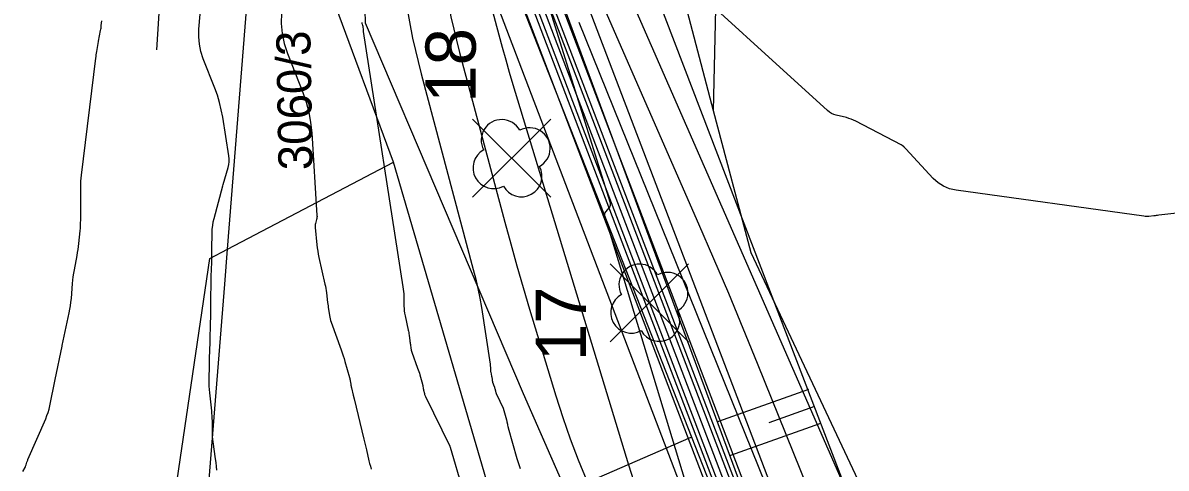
# Model space of a CAD drawing. Extents: x -534410 to -534262, y -1190162 to -1189584.
# Drawn here: x -534375.72 to -534347.25, y -1189924.89 to -1189913.8 of the extents above; entities that cross this region are included whole.
import ezdxf

# ---------------------------------------------------------------- set-up
doc = ezdxf.new("R2010")
doc.units = 0
for name, color, linetype in [('30', 7, 'Continuous'), ('31', 7, 'Continuous'), ('_linie', 7, 'Continuous'), ('_N_osa', 7, 'Continuous'), ('_N_tenká', 7, 'Continuous'), ('_N_tenká_velmi', 7, 'Continuous'), ('_přístup', 7, 'Continuous'), ('_tenka', 7, 'Continuous'), ('_velmi_tenka', 7, 'Continuous'), ('Default', 7, 'Continuous'), ('Hranice parcel', 7, 'Continuous'), ('Parcelní čísla', 7, 'Continuous')]:
    doc.layers.add(name, color=color, linetype=linetype)

msp = doc.modelspace()

# ---------------------------------------------------------------- linework, layer by layer
at = {"layer": '30'}
for points in [[(-534366.318, -1189889.293), (-534365.402, -1189910.932), (-534365.338, -1189911.844), (-534365.225, -1189912.749), (-534365.062, -1189913.646), (-534364.85, -1189914.535), (-534363.721, -1189918.76), (-534363.573, -1189919.304), (-534363.42, -1189919.847), (-534363.263, -1189920.389), (-534363.101, -1189920.929), (-534362.446, -1189923.087), (-534362.275, -1189923.625), (-534362.09, -1189924.157), (-534361.891, -1189924.684), (-534361.678, -1189925.205), (-534360.07, -1189929.007)], [(-534370.89, -1189924.938), (-534370.899, -1189924.845), (-534370.909, -1189924.752), (-534370.922, -1189924.659), (-534370.983, -1189924.231), (-534370.991, -1189924.167), (-534370.997, -1189924.103), (-534371, -1189924.038), (-534371.001, -1189923.974), (-534371.001, -1189923.715), (-534371.002, -1189923.651), (-534371.005, -1189923.586), (-534371.01, -1189923.522), (-534371.016, -1189923.458), (-534371.066, -1189923.011), (-534371.074, -1189922.928), (-534371.079, -1189922.844), (-534371.081, -1189922.761), (-534371.081, -1189922.677), (-534371.075, -1189922.334), (-534371.074, -1189922.254), (-534371.072, -1189922.174), (-534371.07, -1189922.094), (-534371.067, -1189922.015), (-534371.056, -1189921.696), (-534371.054, -1189921.616), (-534371.052, -1189921.536), (-534371.05, -1189921.457), (-534371.048, -1189921.377), (-534371.042, -1189921.018), (-534371.041, -1189920.931), (-534371.04, -1189920.844), (-534371.038, -1189920.758), (-534371.037, -1189920.671), (-534371.032, -1189920.271), (-534371.031, -1189920.201), (-534371.029, -1189920.131), (-534371.028, -1189920.061), (-534371.026, -1189919.992), (-534371.018, -1189919.713), (-534371.017, -1189919.643), (-534371.015, -1189919.573), (-534371.014, -1189919.503), (-534371.013, -1189919.434), (-534371.007, -1189919.027), (-534371.003, -1189918.936), (-534370.993, -1189918.846), (-534370.978, -1189918.757), (-534370.957, -1189918.669), (-534370.737, -1189917.857), (-534370.728, -1189917.826), (-534370.61, -1189917.403), (-534370.594, -1189917.331), (-534370.585, -1189917.259), (-534370.585, -1189917.186), (-534370.593, -1189917.113), (-534370.744, -1189916.148), (-534370.778, -1189915.964), (-534370.822, -1189915.783), (-534370.876, -1189915.604), (-534370.939, -1189915.428), (-534371.227, -1189914.698), (-534371.287, -1189914.516), (-534371.325, -1189914.332), (-534371.341, -1189914.144), (-534371.335, -1189913.953), (-534371.182, -1189912.181)], [(-534362.891, -1189912.541), (-534361.099, -1189918.283), (-534361.093, -1189918.315), (-534361.094, -1189918.345), (-534361.104, -1189918.373), (-534361.122, -1189918.401), (-534361.208, -1189918.506), (-534361.226, -1189918.533), (-534361.235, -1189918.562), (-534361.237, -1189918.592), (-534361.231, -1189918.624), (-534358.587, -1189927.327), (-534358.507, -1189927.579), (-534358.42, -1189927.829), (-534358.327, -1189928.076), (-534358.227, -1189928.32), (-534357.815, -1189929.294), (-534357.714, -1189929.539), (-534357.619, -1189929.785), (-534357.528, -1189930.033), (-534357.442, -1189930.283), (-534355.441, -1189936.3), (-534355.266, -1189936.801)], [(-534355.227, -1189925.422), (-534360.506, -1189913.368)], [(-534367.28, -1189913.791), (-534367.28, -1189913.8), (-534367.279, -1189913.81), (-534367.277, -1189913.82), (-534367.274, -1189913.829), (-534367.26, -1189913.867), (-534367.256, -1189913.876), (-534367.254, -1189913.886), (-534367.252, -1189913.895), (-534367.251, -1189913.905), (-534367.247, -1189913.961), (-534367.247, -1189913.974), (-534367.245, -1189913.986), (-534367.244, -1189913.999), (-534367.242, -1189914.012), (-534366.255, -1189920.37), (-534366.246, -1189920.429), (-534366.24, -1189920.49), (-534366.236, -1189920.55), (-534366.234, -1189920.61), (-534366.231, -1189920.853), (-534366.229, -1189920.913), (-534366.224, -1189920.973), (-534366.215, -1189921.033), (-534366.204, -1189921.092), (-534366.124, -1189921.45), (-534366.117, -1189921.481), (-534366.112, -1189921.512), (-534366.107, -1189921.544), (-534366.102, -1189921.575), (-534366.085, -1189921.715), (-534366.082, -1189921.739), (-534366.078, -1189921.763), (-534366.075, -1189921.787), (-534366.071, -1189921.81), (-534366.057, -1189921.906), (-534366.053, -1189921.929), (-534366.047, -1189921.953), (-534366.041, -1189921.976), (-534366.034, -1189921.998), (-534365.889, -1189922.401), (-534365.875, -1189922.443), (-534365.861, -1189922.485), (-534365.847, -1189922.527), (-534365.835, -1189922.569), (-534365.768, -1189922.8), (-534365.765, -1189922.812), (-534365.762, -1189922.824), (-534365.759, -1189922.836), (-534365.757, -1189922.849), (-534365.75, -1189922.898), (-534365.748, -1189922.91), (-534365.746, -1189922.922), (-534365.743, -1189922.935), (-534365.741, -1189922.947), (-534365.72, -1189923.034), (-534365.715, -1189923.052), (-534365.709, -1189923.07), (-534365.702, -1189923.088), (-534365.694, -1189923.105), (-534365.088, -1189924.346), (-534365.086, -1189924.351), (-534365.082, -1189924.367), (-534364.772, -1189925.413)], [(-534350.654, -1189940.266), (-534350.975, -1189939.571), (-534351.3, -1189938.876), (-534354.616, -1189931.824), (-534354.78, -1189931.466), (-534354.936, -1189931.106), (-534355.086, -1189930.743), (-534355.228, -1189930.376), (-534355.784, -1189928.905), (-534355.924, -1189928.537), (-534356.066, -1189928.171), (-534356.21, -1189927.805), (-534356.356, -1189927.44), (-534361.865, -1189913.788)]]:
    msp.add_lwpolyline(points, dxfattribs=at)
at = {"layer": '31'}
for points in [[(-534346.245, -1189918.455), (-534347.437, -1189918.593), (-534347.468, -1189918.596), (-534347.498, -1189918.6), (-534347.529, -1189918.603), (-534347.56, -1189918.606), (-534347.682, -1189918.619), (-534347.712, -1189918.622), (-534347.743, -1189918.622), (-534347.774, -1189918.621), (-534347.804, -1189918.617), (-534352.484, -1189917.968), (-534352.646, -1189917.932), (-534352.794, -1189917.871), (-534352.929, -1189917.785), (-534353.051, -1189917.673), (-534353.733, -1189916.936), (-534353.748, -1189916.92), (-534353.772, -1189916.893), (-534353.777, -1189916.888), (-534353.782, -1189916.883), (-534353.787, -1189916.879), (-534353.793, -1189916.875), (-534353.823, -1189916.854), (-534353.83, -1189916.849), (-534353.837, -1189916.845), (-534353.844, -1189916.841), (-534353.852, -1189916.837), (-534354.975, -1189916.251), (-534355.033, -1189916.223), (-534355.093, -1189916.199), (-534355.153, -1189916.178), (-534355.215, -1189916.161), (-534355.466, -1189916.099), (-534355.527, -1189916.08), (-534355.584, -1189916.054), (-534355.637, -1189916.021), (-534355.687, -1189915.981), (-534359.811, -1189912.222)], [(-534364.201, -1189912.857), (-534363.869, -1189914.099), (-534363.784, -1189914.409), (-534363.697, -1189914.719), (-534363.608, -1189915.027), (-534363.516, -1189915.335), (-534360.637, -1189924.81), (-534360.449, -1189925.402), (-534360.245, -1189925.989), (-534360.026, -1189926.57), (-534359.791, -1189927.145), (-534359.16, -1189928.636)], [(-534366.182, -1189913.277), (-534366.018, -1189914.179), (-534365.805, -1189915.073), (-534364.503, -1189919.944), (-534364.443, -1189920.179), (-534364.39, -1189920.415), (-534364.343, -1189920.653), (-534364.303, -1189920.892), (-534364.085, -1189922.297), (-534364.082, -1189922.314), (-534364.081, -1189922.33), (-534364.08, -1189922.347), (-534364.079, -1189922.364), (-534364.078, -1189922.43), (-534364.078, -1189922.447), (-534364.076, -1189922.464), (-534364.074, -1189922.48), (-534364.071, -1189922.496), (-534364.049, -1189922.595), (-534364.047, -1189922.604), (-534364.045, -1189922.612), (-534364.044, -1189922.621), (-534364.043, -1189922.629), (-534364.037, -1189922.674), (-534364.034, -1189922.694), (-534364.03, -1189922.72), (-534364.029, -1189922.727), (-534364.028, -1189922.733), (-534364.026, -1189922.74), (-534364.024, -1189922.746), (-534363.984, -1189922.857), (-534363.98, -1189922.868), (-534363.976, -1189922.88), (-534363.972, -1189922.891), (-534363.969, -1189922.903), (-534363.951, -1189922.967), (-534363.949, -1189922.973), (-534363.948, -1189922.98), (-534363.945, -1189922.997), (-534363.943, -1189923.007), (-534363.937, -1189923.031), (-534363.936, -1189923.036), (-534363.934, -1189923.041), (-534363.932, -1189923.046), (-534363.93, -1189923.051), (-534363.763, -1189923.392), (-534363.762, -1189923.398), (-534363.676, -1189923.686), (-534363.673, -1189923.698), (-534363.67, -1189923.709), (-534363.668, -1189923.72), (-534363.665, -1189923.732), (-534363.653, -1189923.793), (-534363.649, -1189923.818), (-534363.643, -1189923.851), (-534363.641, -1189923.86), (-534363.639, -1189923.868), (-534363.637, -1189923.876), (-534363.635, -1189923.885), (-534363.416, -1189924.645), (-534363.377, -1189924.774), (-534363.335, -1189924.901)], [(-534350.063, -1189940.058), (-534350.26, -1189939.632), (-534350.459, -1189939.207), (-534352.036, -1189935.853), (-534352.358, -1189935.15), (-534352.667, -1189934.44), (-534352.961, -1189933.725), (-534353.242, -1189933.004), (-534354.655, -1189929.263), (-534354.984, -1189928.399), (-534355.318, -1189927.536), (-534355.657, -1189926.676), (-534356, -1189925.818), (-534357.425, -1189922.287), (-534357.781, -1189921.414), (-534358.143, -1189920.544), (-534358.512, -1189919.677), (-534358.887, -1189918.812), (-534361.396, -1189913.081)], [(-534369.28, -1189913.554), (-534369.288, -1189913.812), (-534369.266, -1189914.066), (-534369.215, -1189914.315), (-534369.134, -1189914.56), (-534368.751, -1189915.532), (-534368.666, -1189915.778), (-534368.6, -1189916.027), (-534368.554, -1189916.281), (-534368.527, -1189916.54), (-534368.396, -1189918.597), (-534368.395, -1189918.623), (-534368.397, -1189918.648), (-534368.4, -1189918.673), (-534368.406, -1189918.697), (-534368.433, -1189918.795), (-534368.438, -1189918.82), (-534368.442, -1189918.845), (-534368.443, -1189918.87), (-534368.441, -1189918.895), (-534368.398, -1189919.324), (-534368.389, -1189919.404), (-534368.377, -1189919.483), (-534368.364, -1189919.562), (-534368.347, -1189919.64), (-534368.199, -1189920.306), (-534368.188, -1189920.359), (-534368.178, -1189920.413), (-534368.169, -1189920.466), (-534368.162, -1189920.52), (-534368.132, -1189920.762), (-534368.126, -1189920.803), (-534368.121, -1189920.844), (-534368.115, -1189920.886), (-534368.109, -1189920.927), (-534368.084, -1189921.091), (-534368.077, -1189921.131), (-534368.067, -1189921.172), (-534368.056, -1189921.212), (-534368.043, -1189921.251), (-534367.795, -1189921.945), (-534367.769, -1189922.017), (-534367.745, -1189922.089), (-534367.722, -1189922.162), (-534367.701, -1189922.235), (-534367.585, -1189922.633), (-534367.579, -1189922.654), (-534367.575, -1189922.675), (-534367.57, -1189922.696), (-534367.567, -1189922.717), (-534367.555, -1189922.802), (-534367.551, -1189922.823), (-534367.547, -1189922.844), (-534367.543, -1189922.865), (-534367.538, -1189922.886), (-534367.495, -1189923.069), (-534367.472, -1189923.165), (-534367.232, -1189924.165), (-534367.167, -1189924.437), (-534367.102, -1189924.709), (-534367.085, -1189924.776), (-534367.067, -1189924.844), (-534367.049, -1189924.911)], [(-534375.719, -1189924.973), (-534375.665, -1189924.876), (-534375.657, -1189924.86), (-534375.65, -1189924.844), (-534375.643, -1189924.827), (-534375.638, -1189924.81), (-534375.617, -1189924.742), (-534375.612, -1189924.725), (-534375.606, -1189924.709), (-534375.599, -1189924.692), (-534375.593, -1189924.676), (-534375.15, -1189923.659), (-534375.119, -1189923.581), (-534375.091, -1189923.502), (-534375.068, -1189923.422), (-534375.049, -1189923.34), (-534374.913, -1189922.679), (-534374.741, -1189921.848), (-534374.739, -1189921.839), (-534374.565, -1189921.022), (-534374.548, -1189920.933), (-534374.533, -1189920.844), (-534374.521, -1189920.754), (-534374.512, -1189920.663), (-534374.482, -1189920.292), (-534374.473, -1189920.206), (-534374.463, -1189920.121), (-534374.45, -1189920.036), (-534374.436, -1189919.951), (-534374.368, -1189919.59), (-534374.355, -1189919.516), (-534374.344, -1189919.442), (-534374.334, -1189919.367), (-534374.326, -1189919.293), (-534374.294, -1189918.978), (-534374.288, -1189918.911), (-534374.284, -1189918.844), (-534374.281, -1189918.777), (-534374.28, -1189918.711), (-534374.279, -1189918.443), (-534374.279, -1189918.376), (-534374.279, -1189918.309), (-534374.279, -1189918.242), (-534374.279, -1189918.175), (-534374.279, -1189917.881), (-534374.278, -1189917.81), (-534374.275, -1189917.739), (-534374.269, -1189917.668), (-534374.261, -1189917.597), (-534373.902, -1189914.678), (-534373.896, -1189914.637), (-534373.891, -1189914.595), (-534373.885, -1189914.553), (-534373.878, -1189914.512), (-534373.84, -1189914.263), (-534373.839, -1189914.259), (-534373.784, -1189913.987), (-534373.778, -1189913.958), (-534373.773, -1189913.928), (-534373.769, -1189913.898), (-534373.766, -1189913.868), (-534373.753, -1189913.749)]]:
    msp.add_lwpolyline(points, dxfattribs=at)
at = {"layer": '_linie'}
for points in [[(-534366.12, -1189620.81), (-534364.52, -1189627.2), (-534365.69, -1189653.8), (-534366.76, -1189684.81), (-534368.14, -1189748.73), (-534368.38, -1189779.14), (-534368.65, -1189820.64), (-534368.59, -1189847.58), (-534367.2, -1189913.8)], [(-534363.12, -1189621.02), (-534362.79, -1189621.58), (-534361.82, -1189627.79), (-534363.46, -1189653.55), (-534365.47, -1189684.77), (-534366.65, -1189748.83), (-534366.75, -1189779.47), (-534366.9, -1189820.47), (-534366.95, -1189846.72), (-534366.338, -1189888.804), (-534363.85, -1189911.95), (-534357.07, -1189929.19), (-534352.334, -1189940.856)], [(-534359.03, -1189621.26), (-534359.41, -1189621.83), (-534360.84, -1189627.76), (-534362.92, -1189653.56), (-534364.64, -1189685), (-534365.94, -1189748.9), (-534366.02, -1189779.52), (-534366.03, -1189820.5), (-534366.48, -1189846.73), (-534365.511, -1189888.873), (-534362.72, -1189912.12), (-534356.62, -1189928.64), (-534351.589, -1189940.594)], [(-534367.2, -1189913.8), (-534363.26, -1189923.03), (-534359.43, -1189931.78), (-534354.79, -1189941.72)]]:
    msp.add_lwpolyline(points, dxfattribs=at)
at = {"layer": '_N_osa'}
msp.add_lwpolyline([(-534351.95, -1189940.722), (-534356.845, -1189928.915), (-534363.285, -1189912.035), (-534365.925, -1189888.838), (-534366.715, -1189846.725), (-534366.465, -1189820.485), (-534366.385, -1189779.495), (-534366.295, -1189748.865), (-534365.055, -1189684.885), (-534363.19, -1189653.555), (-534361.333, -1189627.822)], dxfattribs=at)
at = {"layer": '_N_tenká'}
for points in [[(-534352.92, -1189941.124), (-534357.821, -1189929.303), (-534364.313, -1189912.285), (-534366.973, -1189888.908), (-534367.765, -1189846.73), (-534367.515, -1189820.479), (-534367.435, -1189779.492), (-534367.345, -1189748.853), (-534366.104, -1189684.844), (-534364.238, -1189653.486), (-534362.424, -1189628.352), (-534361.782, -1189627.792)], [(-534350.98, -1189940.319), (-534355.869, -1189928.527), (-534362.257, -1189911.785), (-534364.876, -1189888.769), (-534365.665, -1189846.72), (-534365.415, -1189820.491), (-534365.335, -1189779.498), (-534365.245, -1189748.877), (-534364.006, -1189684.926), (-534362.142, -1189653.624), (-534360.329, -1189628.488), (-534360.884, -1189627.851)]]:
    msp.add_lwpolyline(points, dxfattribs=at)
at = {"layer": '_N_tenká_velmi'}
for points in [[(-534352.366, -1189940.894), (-534357.263, -1189929.081), (-534363.726, -1189912.142), (-534366.374, -1189888.868), (-534367.165, -1189846.727), (-534366.915, -1189820.482), (-534366.835, -1189779.494), (-534366.745, -1189748.86), (-534365.505, -1189684.867), (-534363.639, -1189653.525), (-534361.782, -1189627.792)], [(-534352.181, -1189940.817), (-534357.077, -1189929.007), (-534363.53, -1189912.095), (-534366.174, -1189888.855), (-534366.965, -1189846.726), (-534366.715, -1189820.484), (-534366.635, -1189779.494), (-534366.545, -1189748.862), (-534365.305, -1189684.875), (-534363.439, -1189653.539), (-534361.583, -1189627.805)], [(-534352.089, -1189940.779), (-534356.984, -1189928.97), (-534363.432, -1189912.071), (-534366.074, -1189888.848), (-534366.865, -1189846.726), (-534366.615, -1189820.484), (-534366.535, -1189779.495), (-534366.445, -1189748.863), (-534365.205, -1189684.879), (-534363.34, -1189653.545), (-534361.483, -1189627.812)], [(-534351.812, -1189940.664), (-534356.706, -1189928.86), (-534363.138, -1189911.999), (-534365.775, -1189888.828), (-534366.565, -1189846.724), (-534366.315, -1189820.486), (-534366.235, -1189779.495), (-534366.145, -1189748.867), (-534364.905, -1189684.891), (-534363.04, -1189653.565), (-534361.184, -1189627.831)], [(-534351.719, -1189940.626), (-534356.613, -1189928.823), (-534363.04, -1189911.975), (-534365.675, -1189888.822), (-534366.465, -1189846.724), (-534366.215, -1189820.486), (-534366.135, -1189779.496), (-534366.045, -1189748.868), (-534364.805, -1189684.895), (-534362.941, -1189653.571), (-534361.084, -1189627.838)], [(-534351.534, -1189940.549), (-534356.427, -1189928.749), (-534362.844, -1189911.928), (-534365.475, -1189888.808), (-534366.265, -1189846.723), (-534366.015, -1189820.488), (-534365.935, -1189779.496), (-534365.845, -1189748.87), (-534364.605, -1189684.903), (-534362.741, -1189653.585), (-534360.884, -1189627.851)]]:
    msp.add_lwpolyline(points, dxfattribs=at)
at = {"layer": '_přístup'}
for p, q in [((-534362.577, -1189918.143), (-534364.523, -1189916.197)), ((-534364.523, -1189918.143), (-534362.577, -1189916.197)), ((-534359.147, -1189921.743), (-534361.093, -1189919.797)), ((-534361.093, -1189921.743), (-534359.147, -1189919.797))]:
    msp.add_line(p, q, dxfattribs=at)
for centre in [(-534363.55, -1189917.17), (-534360.12, -1189920.77)]:
    msp.add_circle(centre, 0.000512, dxfattribs=at)
for centre, start, end in [((-534363.795, -1189916.721), 28.6209, 208.6209), ((-534363.101, -1189916.925), 298.6209, 118.6209), ((-534363.999, -1189917.415), 118.6209, 298.6209), ((-534363.305, -1189917.619), 208.6209, 28.6209), ((-534360.365, -1189920.321), 28.6209, 208.6209), ((-534359.671, -1189920.525), 298.6209, 118.6209), ((-534360.569, -1189921.015), 118.6209, 298.6209), ((-534359.875, -1189921.219), 208.6209, 28.6209)]:
    msp.add_arc(centre, 0.512, start, end, dxfattribs=at)
at = {"layer": '_tenka'}
for points in [[(-534349.13, -1189939.73), (-534354.63, -1189926.96), (-534362.03, -1189907.65), (-534364.521, -1189888.74), (-534364.47, -1189846.64), (-534364.29, -1189820.63), (-534364.22, -1189780.69), (-534363.18, -1189749.38), (-534362.5, -1189685.39), (-534360.27, -1189651.6), (-534357.03, -1189627.34), (-534354.77, -1189620.37)], [(-534366.12, -1189620.81), (-534364.52, -1189627.2), (-534365.69, -1189653.8), (-534366.76, -1189684.81), (-534368.14, -1189748.73), (-534368.38, -1189779.14), (-534368.65, -1189820.64), (-534368.59, -1189847.58), (-534367.2, -1189913.8)], [(-534366.12, -1189620.81), (-534364.52, -1189627.2), (-534365.69, -1189653.8), (-534366.76, -1189684.81), (-534368.14, -1189748.73), (-534368.38, -1189779.14), (-534368.65, -1189820.64), (-534368.59, -1189847.58), (-534367.2, -1189913.8)], [(-534363.12, -1189621.02), (-534362.79, -1189621.58), (-534361.82, -1189627.79), (-534363.46, -1189653.55), (-534365.47, -1189684.77), (-534366.65, -1189748.83), (-534366.75, -1189779.47), (-534366.9, -1189820.47), (-534366.95, -1189846.72), (-534366.338, -1189888.804), (-534363.85, -1189911.95), (-534357.07, -1189929.19), (-534352.334, -1189940.856)], [(-534363.12, -1189621.02), (-534362.79, -1189621.58), (-534361.82, -1189627.79), (-534363.46, -1189653.55), (-534365.47, -1189684.77), (-534366.65, -1189748.83), (-534366.75, -1189779.47), (-534366.9, -1189820.47), (-534366.95, -1189846.72), (-534366.338, -1189888.804), (-534363.85, -1189911.95), (-534357.07, -1189929.19), (-534352.334, -1189940.856)], [(-534359.03, -1189621.26), (-534359.41, -1189621.83), (-534360.84, -1189627.76), (-534362.92, -1189653.56), (-534364.64, -1189685), (-534365.94, -1189748.9), (-534366.02, -1189779.52), (-534366.03, -1189820.5), (-534366.48, -1189846.73), (-534365.511, -1189888.873), (-534362.72, -1189912.12), (-534356.62, -1189928.64), (-534351.589, -1189940.594)], [(-534359.03, -1189621.26), (-534359.41, -1189621.83), (-534360.84, -1189627.76), (-534362.92, -1189653.56), (-534364.64, -1189685), (-534365.94, -1189748.9), (-534366.02, -1189779.52), (-534366.03, -1189820.5), (-534366.48, -1189846.73), (-534365.511, -1189888.873), (-534362.72, -1189912.12), (-534356.62, -1189928.64), (-534351.589, -1189940.594)], [(-534368.65, -1189626.81), (-534368.65, -1189626.81), (-534367.31, -1189654.04), (-534367.67, -1189685.23), (-534369.56, -1189748.93), (-534369.48, -1189778.6), (-534369.45, -1189820.62), (-534369.45, -1189847.87), (-534371.206, -1189896.071), (-534372.39, -1189914.47)], [(-534367.2, -1189913.8), (-534363.26, -1189923.03), (-534359.43, -1189931.78), (-534354.79, -1189941.72)], [(-534367.2, -1189913.8), (-534367.2, -1189913.8), (-534363.26, -1189923.03), (-534359.43, -1189931.78), (-534354.79, -1189941.72)]]:
    msp.add_lwpolyline(points, dxfattribs=at)
at = {"layer": '_velmi_tenka'}
for p, q in [((-534356.161, -1189922.933), (-534358.425, -1189923.735)), ((-534356.011, -1189923.357), (-534357.143, -1189923.758)), ((-534355.861, -1189923.781), (-534358.124, -1189924.583)), ((-534362.19, -1189925.472), (-534359.082, -1189924.118))]:
    msp.add_line(p, q, dxfattribs=at)
at = {"layer": 'Default'}
for p, q in [((-534367.2, -1189913.8), (-534363.26, -1189923.03)), ((-534367.2, -1189913.8), (-534367.2, -1189913.8)), ((-534367.2, -1189913.8), (-534367.2, -1189913.8)), ((-534363.26, -1189923.03), (-534359.43, -1189931.78))]:
    msp.add_line(p, q, dxfattribs=at)
msp.add_lwpolyline([(-534349.13, -1189939.73), (-534354.63, -1189926.96), (-534362.03, -1189907.65), (-534364.521, -1189888.74), (-534364.47, -1189846.64), (-534364.29, -1189820.63), (-534364.22, -1189780.69), (-534363.18, -1189749.38), (-534362.5, -1189685.39), (-534360.27, -1189651.6), (-534357.03, -1189627.34), (-534354.77, -1189620.37)], dxfattribs=at)
at = {"layer": 'Hranice parcel'}
for p, q in [((-534362.34, -1189901.56), (-534358.53, -1189915.98)), ((-534370.62, -1189919.44), (-534369.75, -1189908.47)), ((-534366.49, -1189917.27), (-534369.75, -1189908.47)), ((-534370.62, -1189919.44), (-534366.49, -1189917.27)), ((-534363.5, -1189927.49), (-534366.49, -1189917.27))]:
    msp.add_line(p, q, dxfattribs=at)
for points in [[(-534359.48, -1189697.97), (-534360.42, -1189747.8), (-534359.17, -1189788.69), (-534356.86, -1189843.2), (-534358.53, -1189915.98)], [(-534358.53, -1189915.98), (-534357.59, -1189919.52), (-534354.73, -1189925.6)], [(-534373.8, -1189945.18), (-534374.7, -1189944.34), (-534371.06, -1189919.67), (-534370.62, -1189919.44)], [(-534373, -1189940.81), (-534371.42, -1189929.41), (-534370.69, -1189920.31), (-534370.62, -1189919.44)]]:
    msp.add_lwpolyline(points, dxfattribs=at)

# ---------------------------------------------------------------- texts
at = {"layer": '_přístup'}
for s, p in [('18', (-534364.444, -1189915.789)), ('17', (-534361.701, -1189922.226))]:
    msp.add_text(s, height=1.25, rotation=90, dxfattribs=at).set_placement(p)
at = {"layer": 'Parcelní čísla'}
msp.add_text('3060/3', height=0.85, rotation=91, dxfattribs=at).set_placement((-534368.503, -1189917.462))

doc.saveas('drawing.dxf')
